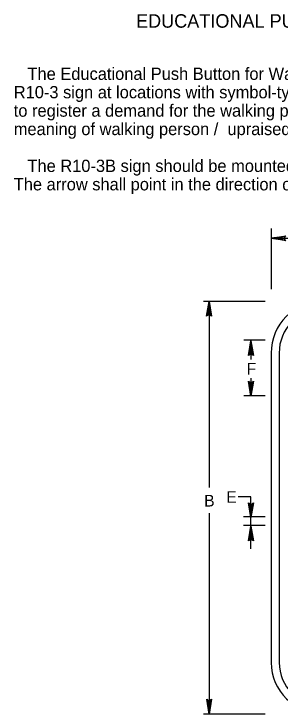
# Model space of a CAD drawing. Extents: x 0.013 to 0.191, y 0.004 to 0.259.
# Drawn here: x 0.0258 to 0.0801, y 0.1074 to 0.2499 of the extents above; entities that cross this region are included whole.
import ezdxf

# ---------------------------------------------------------------- set-up
doc = ezdxf.new("R2010")
doc.units = 0
for name, color, linetype in [('1', 7, 'Continuous'), ('12', 7, 'Continuous'), ('2', 7, 'Continuous'), ('3', 7, 'Continuous')]:
    doc.layers.add(name, color=color, linetype=linetype)

# ---------------------------------------------------------------- blocks, each defined once
blk = doc.blocks.new('RARROW')
at = {"layer": '3'}
for p, q in [((-2.156, 0.28500000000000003), (-2.2665, 0.384625)), ((-2.2665, 0.384625), (0, 0)), ((0, 0), (-2.2665, -0.379125)), ((-2.156, 0.28500000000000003), (-2.075625, 0.12075)), ((0, 0), (-2.156, 0.28500000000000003)), ((-2.14975, -0.2705), (0, 0)), ((-2.075625, 0.12075), (0, 0)), ((0, 0), (-2.074, -0.108)), ((-2.2665, -0.379125), (-2.14975, -0.2705)), ((-2.074, -0.108), (-2.14975, -0.2705))]:
    blk.add_line(p, q, dxfattribs=at)

msp = doc.modelspace()

# ---------------------------------------------------------------- linework, layer by layer
at = {"layer": '1'}
for p, q in [((0.078125, 0.20625000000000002), (0.078125, 0.193875)), ((0.078125, 0.20425000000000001), (0.107125, 0.20425000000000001)), ((0.06432370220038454, 0.19142149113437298), (0.076875, 0.19142149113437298)), ((0.0655, 0.1915), (0.0655, 0.1535)), ((0.0725837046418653, 0.18358148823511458), (0.076875, 0.18358148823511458)), ((0.0739991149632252, 0.18347032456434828), (0.0739991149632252, 0.1795853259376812)), ((0.07399801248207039, 0.17575000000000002), (0.07399801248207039, 0.17226844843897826)), ((0.0725837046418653, 0.17220648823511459), (0.076875, 0.17220648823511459)), ((0.074, 0.15157941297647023), (0.07138538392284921, 0.15157941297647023)), ((0.074, 0.14572888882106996), (0.074, 0.15157941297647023)), ((0.0655, 0.14825), (0.0655, 0.1075)), ((0.076875, 0.1475), (0.0725, 0.1475)), ((0.076875, 0.14575), (0.0725, 0.14575)), ((0.074, 0.1410262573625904), (0.074, 0.14572888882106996)), ((0.06432370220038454, 0.107421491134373), (0.076875, 0.107421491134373))]:
    msp.add_line(p, q, dxfattribs=at)
at = {"layer": '12'}
for p, q in [((0.078125, 0.180875), (0.078125, 0.11787500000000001)), ((0.07975, 0.180875), (0.07975, 0.11787500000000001))]:
    msp.add_line(p, q, dxfattribs=at)
for centre, radius, start, end in [((0.08868749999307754, 0.18091638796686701), 0.01056268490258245, 90.339025, 180.339025), ((0.08868750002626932, 0.18091638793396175), 0.00893771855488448, 90.40066388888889, 180.4006638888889), ((0.0885625, 0.11791638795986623), 0.010437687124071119, 180.34308333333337, 270.34308333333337), ((0.088625, 0.11785388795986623), 0.008875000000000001, 180, 270)]:
    msp.add_arc(centre, radius, start, end, dxfattribs=at)

# ---------------------------------------------------------------- block references
at = {"layer": '3', "xscale": 0.0013236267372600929, "yscale": 0.001309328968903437}
for p, rotation in [((0.078125, 0.20425000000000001), 180), ((0.0655, 0.19137500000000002), 90), ((0.074, 0.183375), 90), ((0.074, 0.172125), -90.00000000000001), ((0.074, 0.147375), -90.00000000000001), ((0.074, 0.145625), 90), ((0.0655, 0.107375), -90.00000000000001)]:
    msp.add_blockref('RARROW', p, dxfattribs=dict(at, rotation=rotation))

# ---------------------------------------------------------------- texts
at = {"layer": '1'}
msp.add_text('EDUCATIONAL PUSH BUTTON FOR WALKING PERSON SIGNAL SIGN', height=0.00275025, dxfattribs=at).set_placement((0.050625, 0.247125))
at = {"layer": '2'}
for s, p in [('   The Educational Push Button for Walking Person Signal Sign (R10-3B) may be used as an alternate to the', (0.025750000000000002, 0.23650025)), ('R10-3 sign at locations with symbol-type pedestrian signal indications where it is desired to permit pedestrians', (0.025750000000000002, 0.2327505)), ('to register a demand for the walking person signal and also to provide an educational message concerning the', (0.025750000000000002, 0.22900075)), ('meaning of walking person /  upraised hand pedestrian signals.', (0.025750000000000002, 0.225251)), ('   The R10-3B sign should be mounted parallel to the desired crossing, immediately above the push button.  ', (0.025750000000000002, 0.2177515)), ('The arrow shall point in the direction of the crossing.', (0.025750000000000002, 0.21400175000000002))]:
    msp.add_text(s, height=0.0024997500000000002, dxfattribs=at).set_placement(p)
at = {"layer": '3'}
for s, p in [('F', (0.073125, 0.1765)), ('E', (0.069, 0.150375)), ('B', (0.0645, 0.149625))]:
    msp.add_text(s, height=0.0023752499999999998, dxfattribs=at).set_placement(p)

doc.saveas('drawing.dxf')
